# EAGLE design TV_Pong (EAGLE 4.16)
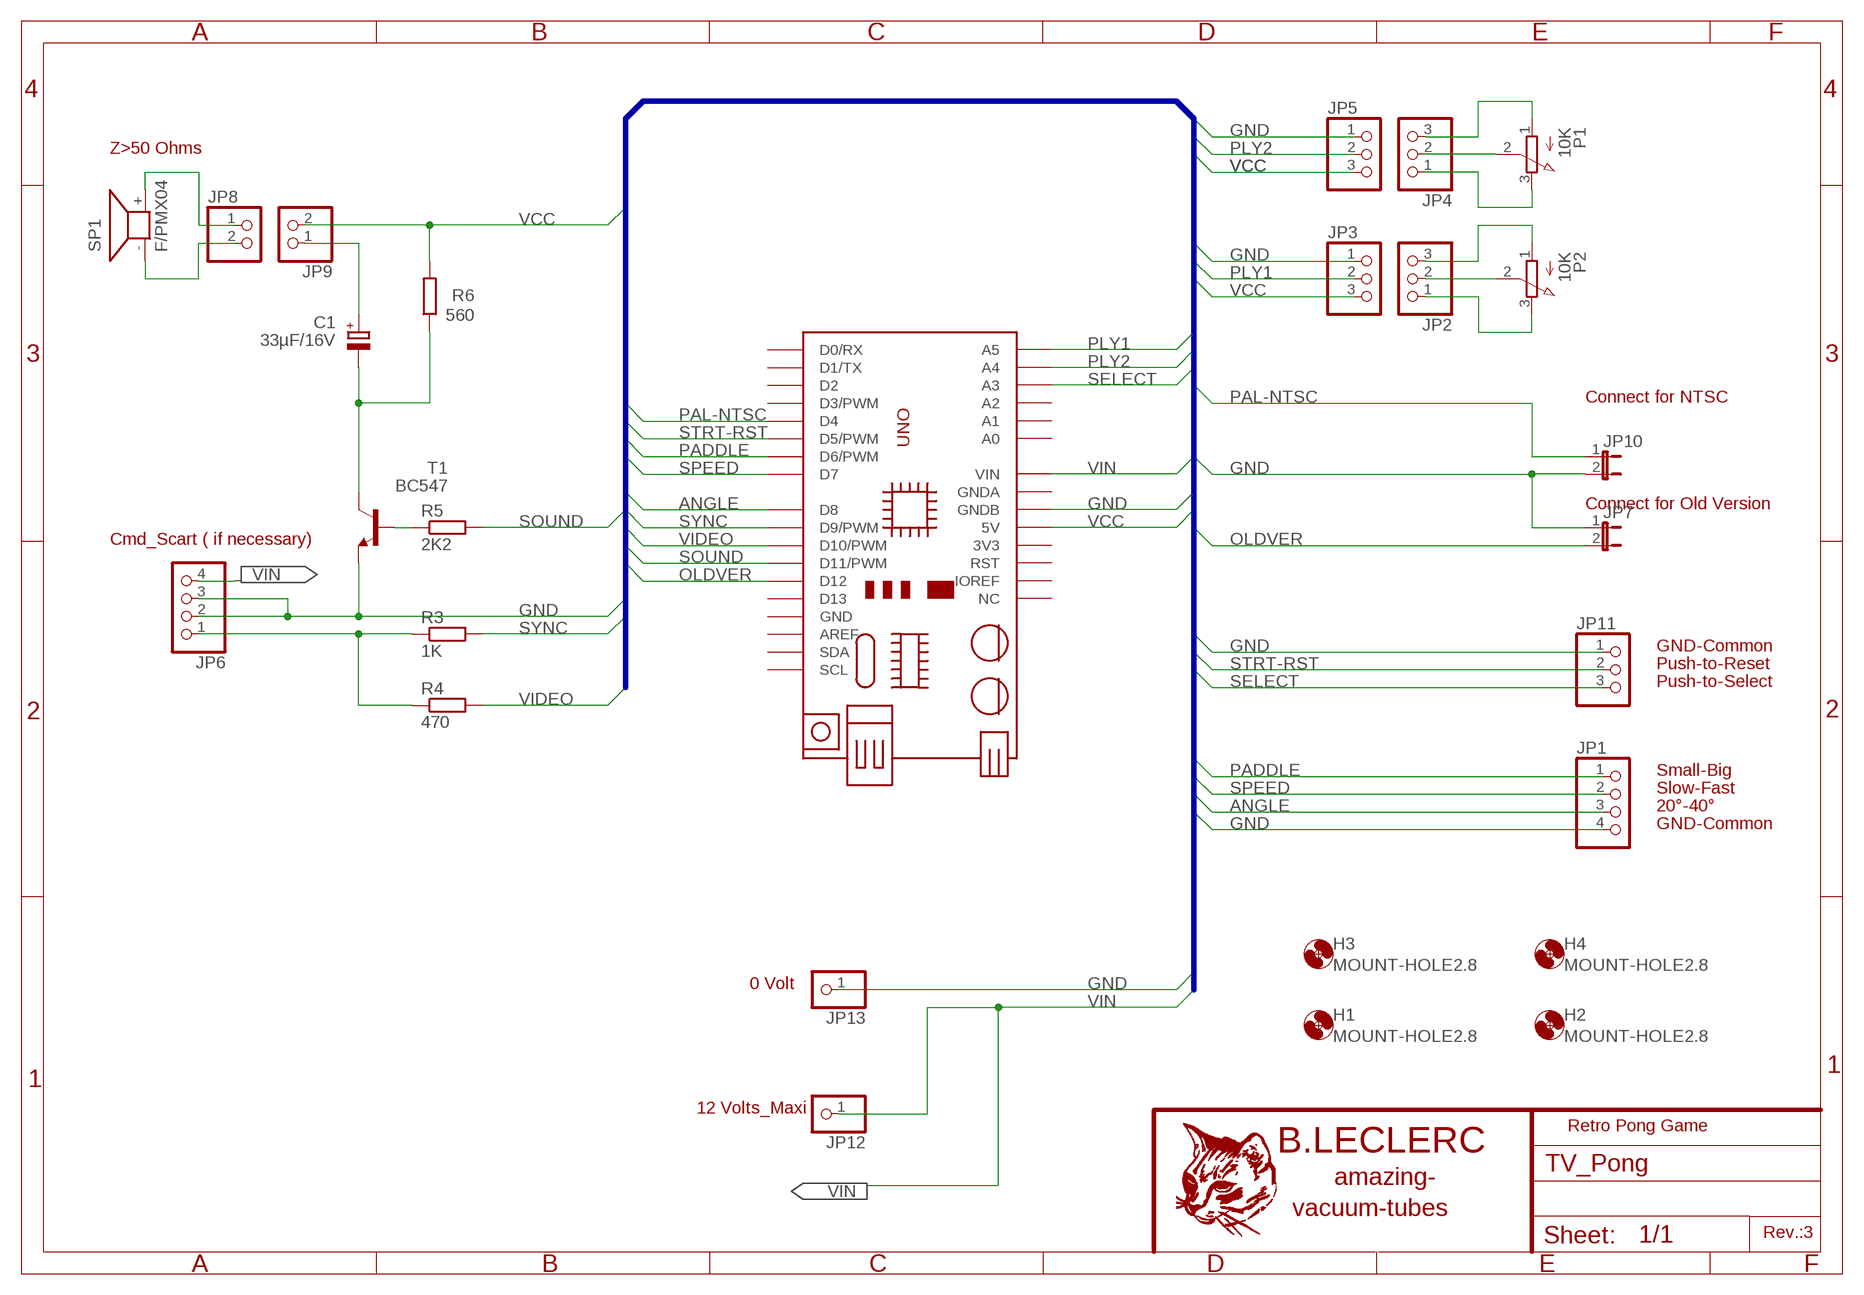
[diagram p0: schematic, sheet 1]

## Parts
C1  33µF/16V  CPOL-EUE2.5-6  [E2,5-6]
H1  MOUNT-HOLE2.8  [2,8]
H2  MOUNT-HOLE2.8  [2,8]
H3  MOUNT-HOLE2.8  [2,8]
H4  MOUNT-HOLE2.8  [2,8]
JP1  PINHD-1X4  [1X04]
JP2  PINHD-1X3  [1X03]
JP3  PINHD-1X3  [1X03]
JP4  PINHD-1X3  [1X03]
JP5  PINHD-1X3  [1X03]
JP6  PINHD-1X4  [1X04]
JP7  JP1E  [JP1]
JP8  PINHD-1X2  [1X02]
JP9  PINHD-1X2  [1X02]
JP10  JP1E  [JP1]
JP11  PINHD-1X3  [1X03]
JP12  PINHD-1X1  [1X01]
JP13  PINHD-1X1  [1X01]
P1  10K  STD-EU  [STD-EU]
P2  10K  STD-EU  [STD-EU]
R3  1K  R-EU_0207/12  [0207/12]
R4  470  R-EU_0207/12  [0207/12]
R5  2K2  R-EU_0207/12  [0207/12]
R6  560  R-EU_0207/12  [0207/12]
SP1  F/PMX04  [F/PMX04A]
T1  BC547  [TO92]
U1  UNO  [UNO]

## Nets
ANGLE: JP1.3 U1.D8
GND: JP1.4 JP3.1 JP5.1 JP6.2 JP6.3 JP7.1 JP10.2 JP11.1 JP13.1 T1.1(E) U1.GNDB
N$7: JP6.1 R3.1 R4.1
N$8: JP8.1 SP1.+
N$9: JP4.2 P1.2(S)
N$10: JP4.3 P1.1(A)
N$11: JP4.1 P1.3(E)
N$12: JP2.3 P2.1(A)
N$13: JP2.2 P2.2(S)
N$14: JP2.1 P2.3(E)
N$15: JP8.2 SP1.-
N$16: C1.- R6.1 T1.3(C)
N$17: R5.1 T1.2(B)
N$41: C1.+ JP9.1
OLDVER: JP7.2 U1.D12
PADDLE: JP1.1 U1.D6(D6/PWM)
PAL-NTSC: JP10.1 U1.D4
PLY1: JP3.2 U1.A5
PLY2: JP5.2 U1.A4
SELECT: JP11.3 U1.A3
SOUND: R5.2 U1.D11(D11/PWM)
SPEED: JP1.2 U1.D7
STRT-RST: JP11.2 U1.D5(D5/PWM)
SYNC: R3.2 U1.D9(D9/PWM)
VCC: JP3.3 JP5.3 JP9.2 R6.2 U1.5V
VIDEO: R4.2 U1.D10(D10/PWM)
VIN: JP6.4 JP12.1 U1.VIN
Unconnected: U1.A0 U1.A1 U1.A2 U1.AREF U1.D0->TX(D0/RX) U1.D1<-RX(D1/TX) U1.D2 U1.D3(D3/PWM) U1.D13 U1.IOREF U1.NC U1.RST U1.SCL U1.SDA

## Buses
B$1

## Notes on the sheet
- Z>50 Ohms
- Connect for NTSC
- Connect for Old Version
- Cmd_Scart ( if necessary)
- GND-Common
- Push-to-Reset
- Push-to-Select
- Small-Big
- Slow-Fast
- 20°-40°
- GND-Common
- 0 Volt
- 12 Volts_Maxi
- Retro Pong Game
- Rev.:3

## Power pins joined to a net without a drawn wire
3V3: U1.3V3
GND: U1.GND
GNDA: U1.GNDA

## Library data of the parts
C1 = rcl:CPOL-EU: POLARIZED CAPACITOR, European symbol
H1-H4 = holes:MOUNT-HOLE: MOUNTING HOLE with drill center marker
JP1 JP6 = pinhead:PINHD-1X4: PIN HEADER
JP2-JP5 JP11 = pinhead:PINHD-1X3: PIN HEADER
JP7 JP10 = jumper:JP1E: JUMPER
JP8 JP9 = pinhead:PINHD-1X2: PIN HEADER
JP12 JP13 = pinhead:PINHD-1X1: PIN HEADER
P1 P2 = pot:STD-EU
R3-R6 = rcl:R-EU_: RESISTOR, European symbol
SP1 = buzzer:F/PMX04: SPEAKER
T1 = transistor:BC547: NPN TRANSISTOR
U1 = Arduino:UNO

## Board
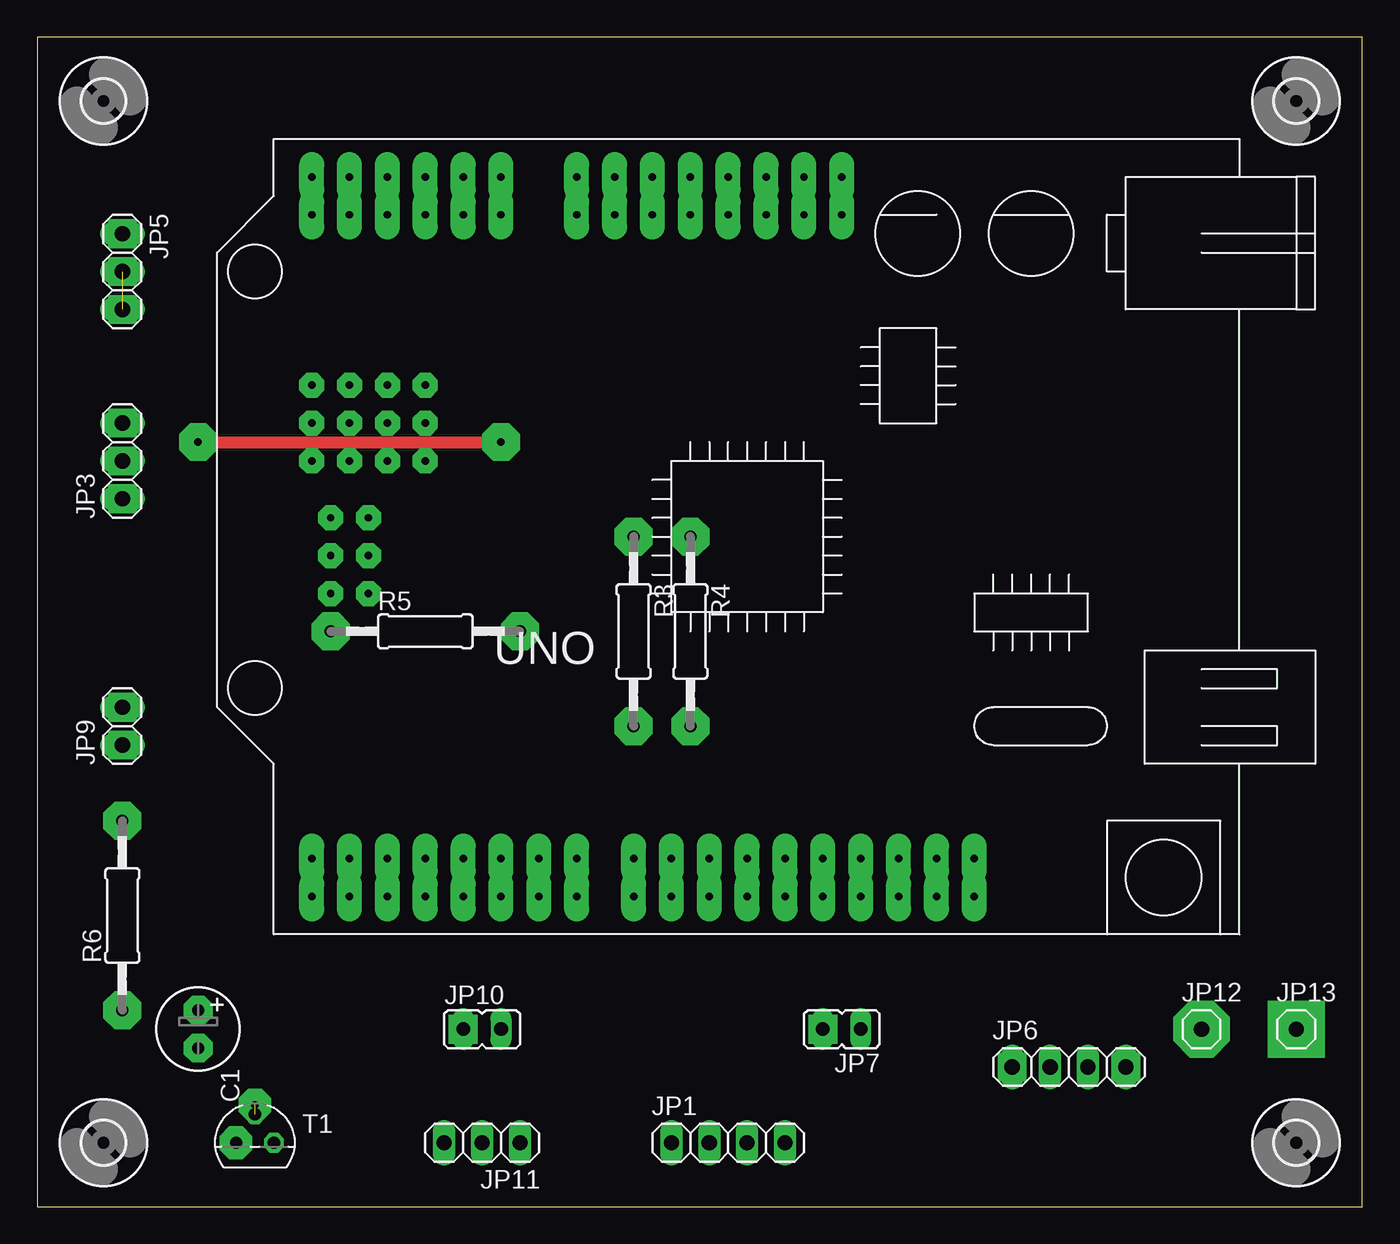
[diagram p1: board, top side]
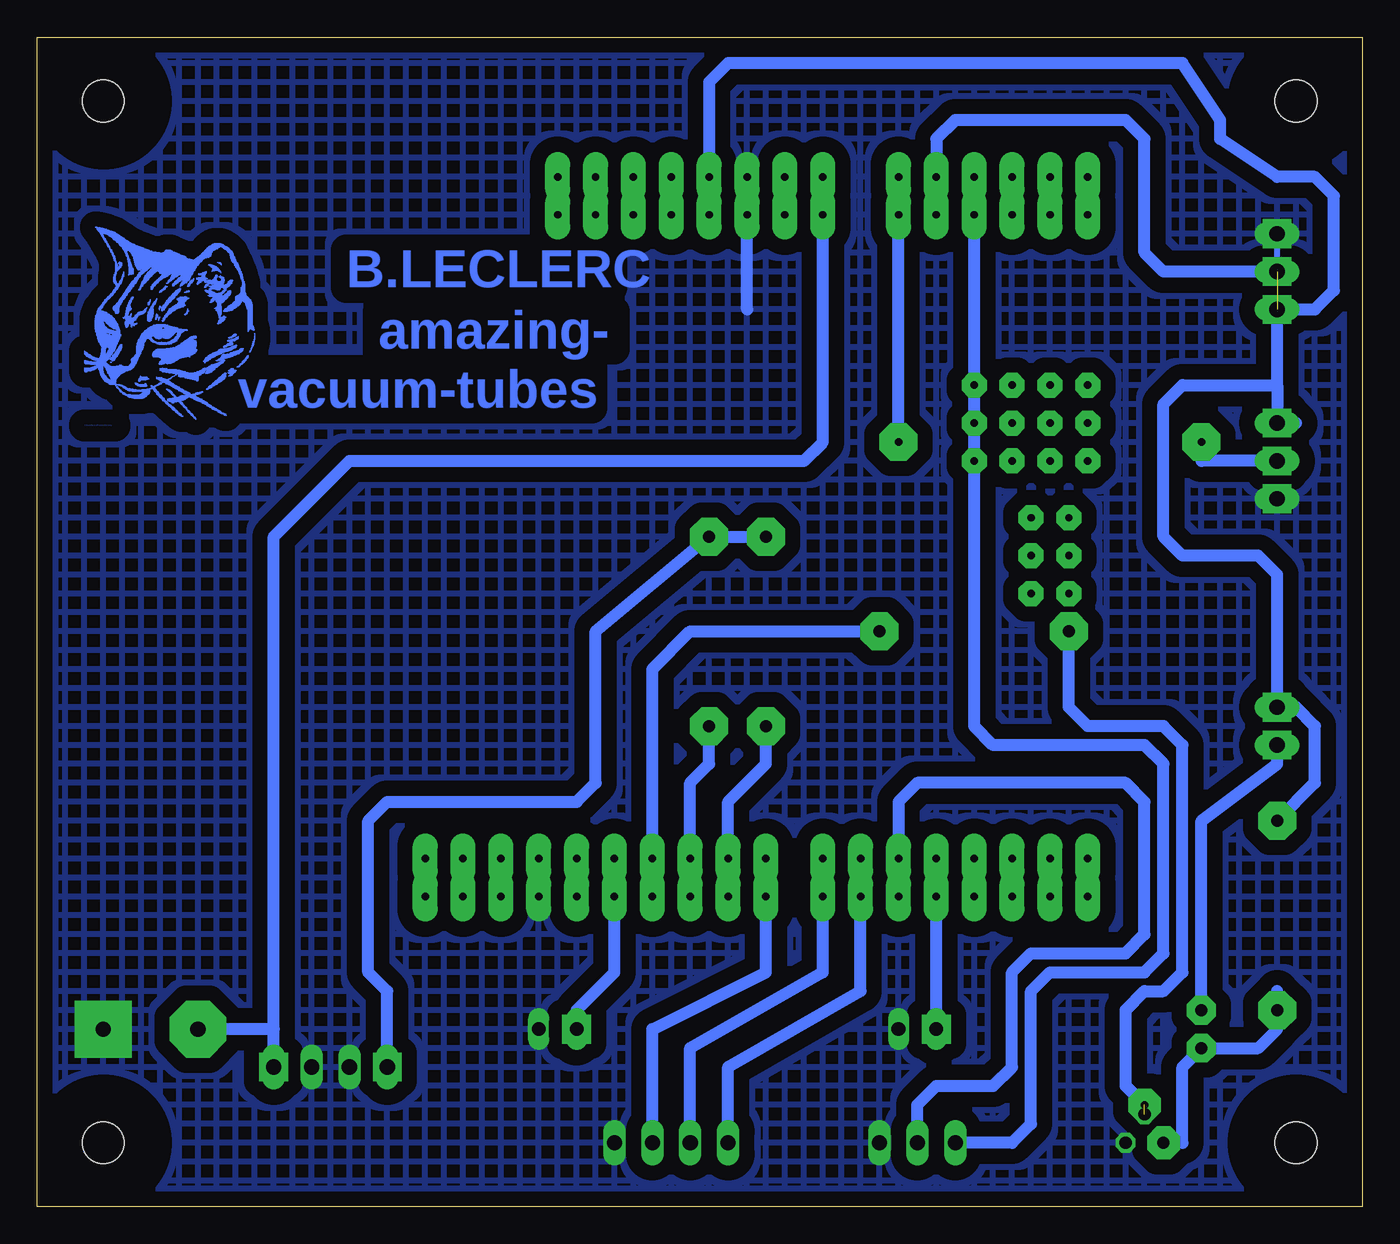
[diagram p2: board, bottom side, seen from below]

Size 88.88 x 78.41 mm. Coordinates in mm from the lower left corner, seen from the top.
Outline: 0,0 88.88,0 88.88,78.41 0,78.41 0,0
Copper layers (1*16): Top 0.035mm / dielectric 1.5mm / Bottom 0.035mm
Design rules "default": minimum track width 10mil, minimum drill 24mil, track to track 8mil, track to pad 8mil, pad to pad 8mil, via to via 8mil, smd to smd 8mil, copper to edge 40mil, drill to drill 8mil, minimum pad ring 10mil, minimum via ring 8mil, stop-mask expansion 4mil, vias tented up to drill 0mil, thermal gap 10mil

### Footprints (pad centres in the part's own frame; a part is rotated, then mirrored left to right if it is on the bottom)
E2,5-6 = drill 0.813 pad 1.6 round: + -1.27,0 | drill 0.813 pad 1.6 octagon: - 1.27,0
2,8 = hole 2.8: 0,0
1X04 = drill 1.016 long: 1 -3.81,0; 2 -1.27,0; 3 1.27,0; 4 3.81,0
1X03 = drill 1.016 long: 1 -2.54,0; 2 0,0; 3 2.54,0
JP1 = drill 0.914 long: 1 0,-1.27; 2 0,1.27
1X02 = drill 1.016 long: 1 -1.27,0; 2 1.27,0
1X01 = drill 1.016 octagon: 1 0,0
STD-EU = drill 0.5 pad 2.184 octagon: 1 -5.08,0; 2 0,0; 3 5.08,0
0207/12 = drill 0.813 octagon: 1 -6.35,0; 2 6.35,0
F/PMX04A = drill 0.914 pad 2.159 octagon: + 3.251,0; - -3.251,0
TO92 = drill 0.813 octagon: 1 1.27,0; 2 0,1.905; 3 -1.27,0
UNO = drill 0.5 pad 1.676 long: 3V3 50.8,34.29; 5V 50.8,36.83; A0 50.8,62.23; A1 50.8,59.69; A2 50.8,57.15; A3 50.8,54.61; A4 50.8,52.07; A5 50.8,49.53; AREF 2.54,22.86; D0->TX 2.54,62.23; D1<-RX 2.54,59.69; D2 2.54,57.15; D3 2.54,54.61; D4 2.54,52.07; D5 2.54,49.53; D6 2.54,46.99; D7 2.54,44.45; D8 2.54,40.64; D9 2.54,38.1; D10 2.54,35.56; D11 2.54,33.02; D12 2.54,30.48; D13 2.54,27.94; GND 2.54,25.4; GNDA 50.8,41.91; GNDB 50.8,39.37; IOREF 50.8,29.21; NC 50.8,26.67; P$33 5.08,62.23; P$34 5.08,59.69; P$35 5.08,57.15; P$36 5.08,54.61; P$37 5.08,52.07; P$38 5.08,49.53; P$39 5.08,46.99; P$40 5.08,44.45; P$41 5.08,40.64; P$42 5.08,38.1; P$43 5.08,35.56; P$44 5.08,33.02; P$45 5.08,30.48; P$46 5.08,27.94; P$47 5.08,25.4; P$48 5.08,22.86; P$49 5.08,20.32; P$50 5.08,17.78; P$51 48.26,26.67; P$52 48.26,29.21; P$53 48.26,31.75; P$54 48.26,34.29; P$55 48.26,36.83; P$56 48.26,39.37; P$57 48.26,41.91; P$58 48.26,44.45; P$59 48.26,49.53; P$60 48.26,52.07; P$61 48.26,54.61; P$62 48.26,57.15; P$63 48.26,59.69; P$64 48.26,62.23; RST 50.8,31.75; SCL 2.54,17.78; SDA 2.54,20.32; VIN 50.8,44.45 | drill 0.5 pad 1.676 octagon: P$65 22.86,60.96; P$66 25.4,60.96; P$67 27.94,60.96; P$68 27.94,58.42; P$69 25.4,58.42; P$70 22.86,58.42; P$71 31.75,59.69; P$72 34.29,59.69; P$73 36.83,59.69; P$74 31.75,62.23; P$75 34.29,62.23; P$76 36.83,62.23; P$77 31.75,57.15; P$78 34.29,57.15; P$79 36.83,57.15; P$80 31.75,54.61; P$81 34.29,54.61; P$82 36.83,54.61

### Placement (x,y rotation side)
C1  10.79,11.9 270 top
H1  4.44,4.28 0 top
H2  84.45,4.28 0 top
H3  4.44,74.13 0 top
H4  84.45,74.13 0 top
JP1  46.35,4.28 0 top
JP2  not placed on the board
JP3  5.71,50 90 top
JP4  not placed on the board
JP5  5.71,62.7 270 top
JP6  69.21,9.36 0 top
JP7  53.97,11.9 90 top
JP8  not placed on the board
JP9  5.71,32.22 90 top
JP10  29.84,11.9 270 top
JP11  29.84,4.28 180 top
JP12  78.1,11.9 0 top
JP13  84.45,11.9 0 top
P1  not placed on the board
P2  not placed on the board
R3  40,38.57 270 top
R4  43.81,38.57 270 top
R5  26.03,38.57 0 top
R6  5.71,19.52 90 top
SP1  not placed on the board
T1  14.6,4.28 0 top
U1  80.64,18.25 90 top
U$2  [CHAT1]  85.72,52.54 0 bottom

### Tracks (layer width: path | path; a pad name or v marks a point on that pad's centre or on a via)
ANGLE
  Bottom 0.813: U1.D8 40,15.71 47.62,11.9 JP1.3
GND  (via drill 0.5 pad 1.93, 0.5 pad 2.54, 0.5 pad 3.81)  (1 unrouted)
  Bottom 0.406: v5.71,62.7 JP5.1
  Bottom 0.813: 41.27,60.16 U1.GNDB
  other vias: 84.45,11.9 84.45,11.9 5.71,47.46 5.71,60.16 5.71,65.24
  pour Bottom (isolate 1.016, no thermals, hatched): 0.63,77.94 88.26,77.94 88.26,0.47 0.63,0.47
N$7
  Bottom 0.813: R3.1 R4.1 51.43,38.57 51.43,28.41 52.7,27.14 65.4,27.14 66.67,25.87 66.67,15.71 65.4,14.44 JP6.1
N$8  (1 unrouted)
N$9  (1 unrouted)
N$10  (1 unrouted)
N$11  (1 unrouted)
N$12  (1 unrouted)
N$13  (1 unrouted)
N$14  (1 unrouted)
N$15  (1 unrouted)
N$16
  Bottom 0.813: T1.3 12.06,4.28 12.06,9.36 C1.- 6.98,10.63 5.71,11.9 R6.1 5.71,14.44
N$17  (1 unrouted)
  Bottom 0.813: R5.1 19.68,33.49 18.41,32.22 13.33,32.22 12.06,30.95 12.06,15.71 13.33,14.44 14.6,14.44 15.87,13.17 15.87,8.09 14.6,6.82
N$18  (via drill 0.5 pad 2.54)
  other vias: 10.79,51.27
N$31  (via drill 0.5 pad 2.54)
  other vias: 32.38,38.57
N$32  (via drill 0.5 pad 2.54)
  other vias: 19.68,38.57
N$41
  Bottom 0.813: JP9.1 5.71,29.68 10.79,25.87 C1.+
N$43  (via drill 0.5 pad 1.93)
  other vias: 5.71,52.54
N$44  (via drill 0.5 pad 1.93)
  other vias: 5.71,50
N$45  (via drill 0.5 pad 3.81)
  other vias: 78.1,11.9
N$46  (via drill 0.5 pad 2.54)
  other vias: 5.71,13.17
N$47  (via drill 0.5 pad 2.54)
  other vias: 43.81,44.92
N$48  (via drill 0.5 pad 2.54)
  other vias: 43.81,32.22
N$49  (via drill 0.5 pad 2.54)
  other vias: 40,44.92
N$50  (via drill 0.5 pad 2.54)
  other vias: 40,32.22
N$51  (via drill 0.5 pad 2.18)
  other vias: 13.33,4.28
N$52  (via drill 0.5 pad 2.18)
  other vias: 14.6,6.82
N$53  (via drill 0.5 pad 1.93)
  other vias: 5.71,33.49
N$54  (via drill 0.5 pad 1.93)
  other vias: 5.71,30.95
N$55  (via drill 0.5 pad 1.93)
  other vias: 28.57,11.9
N$56  (via drill 0.5 pad 2.54)
  other vias: 5.71,25.87
N$57  (via drill 0.5 pad 1.93)
  other vias: 52.7,11.9
N$58  (via drill 0.5 pad 1.93)
  other vias: 10.79,13.17
N$65  (via drill 0.5 pad 1.93)
  other vias: 65.4,9.36
N$66  (via drill 0.5 pad 1.93)
  other vias: 10.79,10.63
N$67  (via drill 0.5 pad 1.93)
  other vias: 73.02,9.36
OLDVER
  Bottom 0.813: U1.D12 50.16,15.71 52.7,13.17 JP7.2
PADDLE
  Bottom 0.813: U1.D6 33.65,14.44 42.54,9.36 JP1.1
PAL-NTSC
  Bottom 0.813: U1.D4 28.57,16.98 28.57,15.71 JP10.1
PLY1  (via drill 0.5 pad 2.54)
  Top 0.813: v10.79,51.27 v31.11,51.27
  Bottom 0.813: v10.79,51.27 10.79,50 JP3.2 | v31.11,51.27 U1.A5
PLY2
  Bottom 0.813: U1.A4 28.57,71.59 27.3,72.86 15.87,72.86 14.6,71.59 14.6,63.97 13.33,62.7 JP5.2
SELECT
  Bottom 0.813: U1.A3 26.03,32.22 24.76,30.95 14.6,30.95 13.33,29.68 13.33,16.98 14.6,15.71 20.95,15.71 22.22,14.44 22.22,5.55 23.49,4.28 JP11.3
SOUND
  Bottom 0.813: R5.2 45.08,38.57 47.62,36.03 U1.D11
SPEED
  Bottom 0.813: U1.D7 36.19,15.71 45.08,10.63 JP1.2
STRT-RST
  Bottom 0.813: U1.D5 31.11,27.14 29.84,28.41 15.87,28.41 14.6,27.14 14.6,18.25 15.87,16.98 22.22,16.98 23.49,15.71 23.49,9.36 24.76,8.09 28.57,8.09 29.84,6.82 JP11.2
SYNC
  Bottom 0.813: R3.2 40,29.68 42.54,27.14 U1.D9
VCC
  Bottom 0.813: R6.2 3.17,28.41 3.17,32.22 4.44,33.49 JP9.2 5.71,42.38 6.98,43.65 12.06,43.65 13.33,44.92 13.33,53.81 12.06,55.08 5.71,55.08 | 5.71,55.08 JP3.3 4.44,52.54 | 5.71,55.08 JP5.3 3.17,60.16 1.9,61.43 1.9,67.78 3.17,69.05 5.71,69.05 9.52,71.59 9.52,72.86 12.06,76.67 42.54,76.67 43.81,75.4 U1.5V
VIDEO
  Bottom 0.813: R4.2 43.81,29.68 45.08,28.41 U1.D10
VIN
  Bottom 0.813: U1.VIN 36.19,51.27 37.46,50 67.94,50 73.02,44.92 73.02,11.9 | JP6.4 73.02,11.9 | 73.02,11.9 JP12.1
